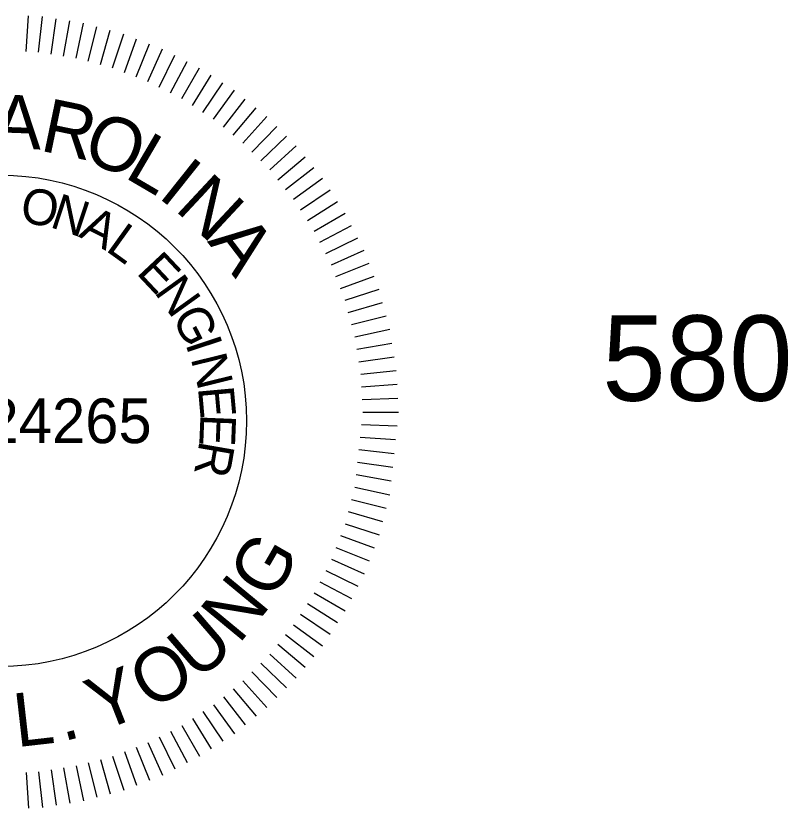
# Model space of a CAD drawing. Extents: x 1964849 to 1967422, y 1116563 to 1122210.
# Drawn here: x 1967345 to 1967421.9, y 1121585 to 1121663.9 of the extents above; entities that cross this region are included whole.
import ezdxf

# ---------------------------------------------------------------- set-up
doc = ezdxf.new("R2010")
doc.units = 0
doc.layers.add('RD_DDB_Profile_Elev', color=7, linetype='Continuous')
doc.layers.add('RD_TX_PEShield', color=7, linetype='Continuous')

msp = doc.modelspace()

# ---------------------------------------------------------------- linework, layer by layer
at = {"layer": 'RD_TX_PEShield'}
for p, q in [((1967346.041, 1121660.368), (1967346.289, 1121663.915)), ((1967346.041, 1121660.368), (1967346.289, 1121663.915)), ((1967347.297, 1121660.302), (1967347.669, 1121663.843)), ((1967347.297, 1121660.302), (1967347.669, 1121663.843)), ((1967348.54, 1121660.105), (1967349.035, 1121663.626)), ((1967348.54, 1121660.105), (1967349.035, 1121663.626)), ((1967349.781, 1121659.909), (1967350.398, 1121663.41)), ((1967349.781, 1121659.909), (1967350.398, 1121663.41)), ((1967351.024, 1121659.712), (1967351.764, 1121663.194)), ((1967351.024, 1121659.712), (1967351.764, 1121663.194)), ((1967351.024, 1121659.712), (1967351.764, 1121663.194)), ((1967352.239, 1121659.386), (1967353.099, 1121662.836)), ((1967352.239, 1121659.386), (1967353.099, 1121662.836)), ((1967352.239, 1121659.386), (1967353.099, 1121662.836)), ((1967353.453, 1121659.061), (1967354.433, 1121662.479)), ((1967353.453, 1121659.061), (1967354.433, 1121662.479)), ((1967353.453, 1121659.061), (1967354.433, 1121662.479)), ((1967354.668, 1121658.735), (1967355.768, 1121662.121)), ((1967354.668, 1121658.735), (1967355.768, 1121662.121)), ((1967354.668, 1121658.735), (1967355.768, 1121662.121)), ((1967355.842, 1121658.284), (1967357.059, 1121661.626)), ((1967355.842, 1121658.284), (1967357.059, 1121661.626)), ((1967355.842, 1121658.284), (1967357.059, 1121661.626)), ((1967357.016, 1121657.834), (1967358.348, 1121661.131)), ((1967357.016, 1121657.834), (1967358.348, 1121661.131)), ((1967357.016, 1121657.834), (1967358.348, 1121661.131)), ((1967358.19, 1121657.383), (1967359.638, 1121660.635)), ((1967358.19, 1121657.383), (1967359.638, 1121660.635)), ((1967358.19, 1121657.383), (1967359.638, 1121660.635)), ((1967359.311, 1121656.812), (1967360.87, 1121660.008)), ((1967359.311, 1121656.812), (1967360.87, 1121660.008)), ((1967359.311, 1121656.812), (1967360.87, 1121660.008)), ((1967360.431, 1121656.242), (1967362.1, 1121659.381)), ((1967360.431, 1121656.242), (1967362.1, 1121659.381)), ((1967360.431, 1121656.242), (1967362.1, 1121659.381)), ((1967361.552, 1121655.67), (1967363.332, 1121658.753)), ((1967361.552, 1121655.67), (1967363.332, 1121658.753)), ((1967361.552, 1121655.67), (1967363.332, 1121658.753)), ((1967362.607, 1121654.985), (1967364.491, 1121658.001)), ((1967362.607, 1121654.985), (1967364.491, 1121658.001)), ((1967362.607, 1121654.985), (1967364.491, 1121658.001)), ((1967363.661, 1121654.301), (1967365.649, 1121657.249)), ((1967363.661, 1121654.301), (1967365.649, 1121657.249)), ((1967363.661, 1121654.301), (1967365.649, 1121657.249)), ((1967364.716, 1121653.616), (1967366.809, 1121656.496)), ((1967364.716, 1121653.616), (1967366.809, 1121656.496)), ((1967364.716, 1121653.616), (1967366.809, 1121656.496)), ((1967365.694, 1121652.824), (1967367.883, 1121655.626)), ((1967365.694, 1121652.824), (1967367.883, 1121655.626)), ((1967365.694, 1121652.824), (1967367.883, 1121655.626)), ((1967366.67, 1121652.033), (1967368.956, 1121654.757)), ((1967366.67, 1121652.033), (1967368.956, 1121654.757)), ((1967366.67, 1121652.033), (1967368.956, 1121654.757)), ((1967367.648, 1121651.241), (1967370.03, 1121653.887)), ((1967367.648, 1121651.241), (1967370.03, 1121653.887)), ((1967367.648, 1121651.241), (1967370.03, 1121653.887)), ((1967368.538, 1121650.352), (1967371.008, 1121652.909)), ((1967368.538, 1121650.352), (1967371.008, 1121652.909)), ((1967368.538, 1121650.352), (1967371.008, 1121652.909)), ((1967369.426, 1121649.463), (1967371.984, 1121651.933)), ((1967369.426, 1121649.463), (1967371.984, 1121651.933)), ((1967369.426, 1121649.463), (1967371.984, 1121651.933)), ((1967370.316, 1121648.573), (1967372.962, 1121650.955)), ((1967370.316, 1121648.573), (1967372.962, 1121650.955)), ((1967370.316, 1121648.573), (1967372.962, 1121650.955)), ((1967371.108, 1121647.596), (1967373.832, 1121649.881)), ((1967371.108, 1121647.596), (1967373.832, 1121649.881)), ((1967371.108, 1121647.596), (1967373.832, 1121649.881)), ((1967371.899, 1121646.619), (1967374.7, 1121648.808)), ((1967371.899, 1121646.619), (1967374.7, 1121648.808)), ((1967371.899, 1121646.619), (1967374.7, 1121648.808)), ((1967372.69, 1121645.641), (1967375.57, 1121647.734)), ((1967372.69, 1121645.641), (1967375.57, 1121647.734)), ((1967372.69, 1121645.641), (1967375.57, 1121647.734)), ((1967373.376, 1121644.586), (1967376.323, 1121646.574)), ((1967373.376, 1121644.586), (1967376.323, 1121646.574)), ((1967373.376, 1121644.586), (1967376.323, 1121646.574)), ((1967374.06, 1121643.532), (1967377.075, 1121645.416)), ((1967374.06, 1121643.532), (1967377.075, 1121645.416)), ((1967374.06, 1121643.532), (1967377.075, 1121645.416)), ((1967374.745, 1121642.477), (1967377.828, 1121644.257)), ((1967374.745, 1121642.477), (1967377.828, 1121644.257)), ((1967374.745, 1121642.477), (1967377.828, 1121644.257)), ((1967375.316, 1121641.356), (1967378.456, 1121643.025)), ((1967375.316, 1121641.356), (1967378.456, 1121643.025)), ((1967375.316, 1121641.356), (1967378.456, 1121643.025)), ((1967375.887, 1121640.236), (1967379.083, 1121641.795)), ((1967375.887, 1121640.236), (1967379.083, 1121641.795)), ((1967375.887, 1121640.236), (1967379.083, 1121641.795)), ((1967376.458, 1121639.115), (1967379.71, 1121640.563)), ((1967376.458, 1121639.115), (1967379.71, 1121640.563)), ((1967376.458, 1121639.115), (1967379.71, 1121640.563)), ((1967376.909, 1121637.941), (1967380.206, 1121639.273)), ((1967376.909, 1121637.941), (1967380.206, 1121639.273)), ((1967376.909, 1121637.941), (1967380.206, 1121639.273)), ((1967377.359, 1121636.768), (1967380.701, 1121637.984)), ((1967377.359, 1121636.768), (1967380.701, 1121637.984)), ((1967377.359, 1121636.768), (1967380.701, 1121637.984)), ((1967377.81, 1121635.593), (1967381.196, 1121636.693)), ((1967377.81, 1121635.593), (1967381.196, 1121636.693)), ((1967377.81, 1121635.593), (1967381.196, 1121636.693)), ((1967378.136, 1121634.378), (1967381.554, 1121635.358)), ((1967378.136, 1121634.378), (1967381.554, 1121635.358)), ((1967378.136, 1121634.378), (1967381.554, 1121635.358)), ((1967378.461, 1121633.164), (1967381.911, 1121634.024)), ((1967378.461, 1121633.164), (1967381.911, 1121634.024)), ((1967378.461, 1121633.164), (1967381.911, 1121634.024)), ((1967378.787, 1121631.949), (1967382.269, 1121632.689)), ((1967378.787, 1121631.949), (1967382.269, 1121632.689)), ((1967378.787, 1121631.949), (1967382.269, 1121632.689)), ((1967378.983, 1121630.706), (1967382.485, 1121631.323)), ((1967378.983, 1121630.706), (1967382.485, 1121631.323)), ((1967378.983, 1121630.706), (1967382.485, 1121631.323)), ((1967379.18, 1121629.465), (1967382.701, 1121629.96)), ((1967379.18, 1121629.465), (1967382.701, 1121629.96)), ((1967379.18, 1121629.465), (1967382.701, 1121629.96)), ((1967379.377, 1121628.222), (1967382.917, 1121628.594)), ((1967379.377, 1121628.222), (1967382.917, 1121628.594)), ((1967379.377, 1121628.222), (1967382.917, 1121628.594)), ((1967379.443, 1121626.966), (1967382.99, 1121627.214)), ((1967379.443, 1121626.966), (1967382.99, 1121627.214)), ((1967379.443, 1121626.966), (1967382.99, 1121627.214)), ((1967379.508, 1121625.711), (1967383.062, 1121625.835)), ((1967379.508, 1121625.711), (1967383.062, 1121625.835)), ((1967379.508, 1121625.711), (1967383.062, 1121625.835)), ((1967379.574, 1121624.454), (1967383.134, 1121624.454)), ((1967379.574, 1121624.454), (1967383.134, 1121624.454)), ((1967379.574, 1121624.454), (1967383.134, 1121624.454)), ((1967379.443, 1121623.2), (1967382.989, 1121623.077)), ((1967379.443, 1121623.2), (1967382.989, 1121623.077)), ((1967379.311, 1121621.952), (1967382.845, 1121621.705)), ((1967379.311, 1121621.952), (1967382.845, 1121621.705)), ((1967379.18, 1121620.707), (1967382.702, 1121620.337)), ((1967379.18, 1121620.707), (1967382.702, 1121620.337)), ((1967379.05, 1121619.462), (1967382.558, 1121618.969)), ((1967379.05, 1121619.462), (1967382.558, 1121618.969)), ((1967378.918, 1121618.214), (1967382.414, 1121617.598)), ((1967378.918, 1121618.214), (1967382.414, 1121617.598)), ((1967378.787, 1121616.96), (1967382.269, 1121616.22)), ((1967378.787, 1121616.96), (1967382.269, 1121616.22)), ((1967378.461, 1121615.745), (1967381.911, 1121614.885)), ((1967378.461, 1121615.745), (1967381.911, 1121614.885)), ((1967378.136, 1121614.531), (1967381.554, 1121613.551)), ((1967378.136, 1121614.531), (1967381.554, 1121613.551)), ((1967377.81, 1121613.316), (1967381.196, 1121612.216)), ((1967377.81, 1121613.316), (1967381.196, 1121612.216)), ((1967377.359, 1121612.141), (1967380.701, 1121610.925)), ((1967377.359, 1121612.141), (1967380.701, 1121610.925)), ((1967376.909, 1121610.968), (1967380.206, 1121609.636)), ((1967376.909, 1121610.968), (1967380.206, 1121609.636)), ((1967376.458, 1121609.794), (1967379.71, 1121608.346)), ((1967376.458, 1121609.794), (1967379.71, 1121608.346)), ((1967375.887, 1121608.673), (1967379.083, 1121607.114)), ((1967375.887, 1121608.673), (1967379.083, 1121607.114)), ((1967375.316, 1121607.553), (1967378.456, 1121605.884)), ((1967375.316, 1121607.553), (1967378.456, 1121605.884)), ((1967374.745, 1121606.432), (1967377.828, 1121604.652)), ((1967374.745, 1121606.432), (1967377.828, 1121604.652)), ((1967374.06, 1121605.377), (1967377.075, 1121603.493)), ((1967374.06, 1121605.377), (1967377.075, 1121603.493)), ((1967373.376, 1121604.323), (1967376.323, 1121602.335)), ((1967373.376, 1121604.323), (1967376.323, 1121602.335)), ((1967372.69, 1121603.268), (1967375.57, 1121601.175)), ((1967372.69, 1121603.268), (1967375.57, 1121601.175)), ((1967371.899, 1121602.29), (1967374.7, 1121600.101)), ((1967371.899, 1121602.29), (1967374.7, 1121600.101)), ((1967371.108, 1121601.313), (1967373.832, 1121599.028)), ((1967371.108, 1121601.313), (1967373.832, 1121599.028)), ((1967370.316, 1121600.336), (1967372.962, 1121597.954)), ((1967370.316, 1121600.336), (1967372.962, 1121597.954)), ((1967369.426, 1121599.446), (1967371.984, 1121596.976)), ((1967369.426, 1121599.446), (1967371.984, 1121596.976)), ((1967368.538, 1121598.557), (1967371.008, 1121596)), ((1967368.538, 1121598.557), (1967371.008, 1121596)), ((1967367.648, 1121597.668), (1967370.03, 1121595.022)), ((1967366.67, 1121596.876), (1967368.956, 1121594.152)), ((1967366.67, 1121596.876), (1967368.956, 1121594.152)), ((1967365.694, 1121596.085), (1967367.883, 1121593.283)), ((1967365.694, 1121596.085), (1967367.883, 1121593.283)), ((1967364.716, 1121595.293), (1967366.809, 1121592.413)), ((1967364.716, 1121595.293), (1967366.809, 1121592.413)), ((1967363.661, 1121594.608), (1967365.649, 1121591.66)), ((1967363.661, 1121594.608), (1967365.649, 1121591.66)), ((1967362.607, 1121593.924), (1967364.491, 1121590.908)), ((1967362.607, 1121593.924), (1967364.491, 1121590.908)), ((1967361.552, 1121593.239), (1967363.332, 1121590.156)), ((1967361.552, 1121593.239), (1967363.332, 1121590.156)), ((1967360.431, 1121592.667), (1967362.1, 1121589.528)), ((1967360.431, 1121592.667), (1967362.1, 1121589.528)), ((1967358.19, 1121591.526), (1967359.638, 1121588.274)), ((1967358.19, 1121591.526), (1967359.638, 1121588.274)), ((1967359.311, 1121592.097), (1967360.87, 1121588.901)), ((1967359.311, 1121592.097), (1967360.87, 1121588.901)), ((1967355.842, 1121590.625), (1967357.059, 1121587.283)), ((1967355.842, 1121590.625), (1967357.059, 1121587.283)), ((1967357.016, 1121591.075), (1967358.348, 1121587.778)), ((1967357.016, 1121591.075), (1967358.348, 1121587.778)), ((1967353.453, 1121589.848), (1967354.433, 1121586.43)), ((1967353.453, 1121589.848), (1967354.433, 1121586.43)), ((1967354.668, 1121590.174), (1967355.768, 1121586.788)), ((1967354.668, 1121590.174), (1967355.768, 1121586.788)), ((1967349.781, 1121589), (1967350.398, 1121585.499)), ((1967349.781, 1121589), (1967350.398, 1121585.499)), ((1967351.024, 1121589.197), (1967351.764, 1121585.715)), ((1967351.024, 1121589.197), (1967351.764, 1121585.715)), ((1967352.239, 1121589.523), (1967353.099, 1121586.073)), ((1967352.239, 1121589.523), (1967353.099, 1121586.073)), ((1967346.041, 1121588.541), (1967346.289, 1121584.994)), ((1967346.041, 1121588.541), (1967346.289, 1121584.994)), ((1967347.297, 1121588.607), (1967347.669, 1121585.066)), ((1967347.297, 1121588.607), (1967347.669, 1121585.066)), ((1967348.54, 1121588.804), (1967349.035, 1121585.283)), ((1967348.54, 1121588.804), (1967349.035, 1121585.283))]:
    msp.add_line(p, q, dxfattribs=at)
msp.add_circle((1967343.529, 1121623.576), 24.475, dxfattribs=at)

# ---------------------------------------------------------------- texts
at = {"layer": 'RD_DDB_Profile_Elev'}
msp.add_text('580', height=8.5, dxfattribs=at).set_placement((1967403.423, 1121625.576))
at = {"layer": 'RD_TX_PEShield'}
for s, height, rotation, p in [('A', 5.34, 357.94482, (1967342.739, 1121650.767)), ('R', 5.34, 348.26699, (1967347.321, 1121650.513)), ('O', 5.34, 339.32858, (1967351.46, 1121649.597)), ('L', 5.34, 329.65075, (1967355.721, 1121647.893)), ('I', 5.34, 321.46627, (1967359.059, 1121645.91)), ('N', 5.34, 317.00069, (1967360.751, 1121644.633)), ('O', 3.56, 350.40454, (1967345.328, 1121643.401)), ('N', 3.56, 341.70291, (1967348.307, 1121642.901)), ('A', 3.56, 333.00129, (1967351.175, 1121641.955)), ('L', 3.56, 324.29966, (1967353.868, 1121640.587)), ('A', 5.34, 307.32286, (1967364.046, 1121641.438)), ('E', 3.56, 313.22511, (1967356.943, 1121638.284)), ('N', 3.56, 305.73175, (1967358.747, 1121636.409)), ('G', 3.56, 297.03012, (1967360.513, 1121633.96)), ('I', 3.56, 288.3285, (1967361.888, 1121631.271)), ('N', 3.56, 283.84405, (1967362.434, 1121629.812)), ('E', 3.56, 275.14243, (1967363.159, 1121626.88)), ('E', 3.56, 267.64906, (1967363.423, 1121624.292)), ('R', 3.56, 260.15569, (1967363.346, 1121621.691)), ('G', 5.34, 60.11131, (1967370.639, 1121605.553)), ('N', 5.34, 50.43348, (1967367.223, 1121601.252)), ('U', 5.34, 40.75564, (1967363.133, 1121597.587)), ('O', 5.34, 31.07781, (1967358.485, 1121594.661)), ('Y', 5.34, 21.39998, (1967353.411, 1121592.558)), ('L', 5.34, 6.51713, (1967345.113, 1121591.061)), ('.', 5.34, 14.70161, (1967349.725, 1121591.618))]:
    msp.add_text(s, height=height, rotation=rotation, dxfattribs=at).set_placement(p)
msp.add_text('NO. 24265', height=4.4501, dxfattribs=at).set_placement((1967329.776, 1121621.351))

doc.saveas('drawing.dxf')
